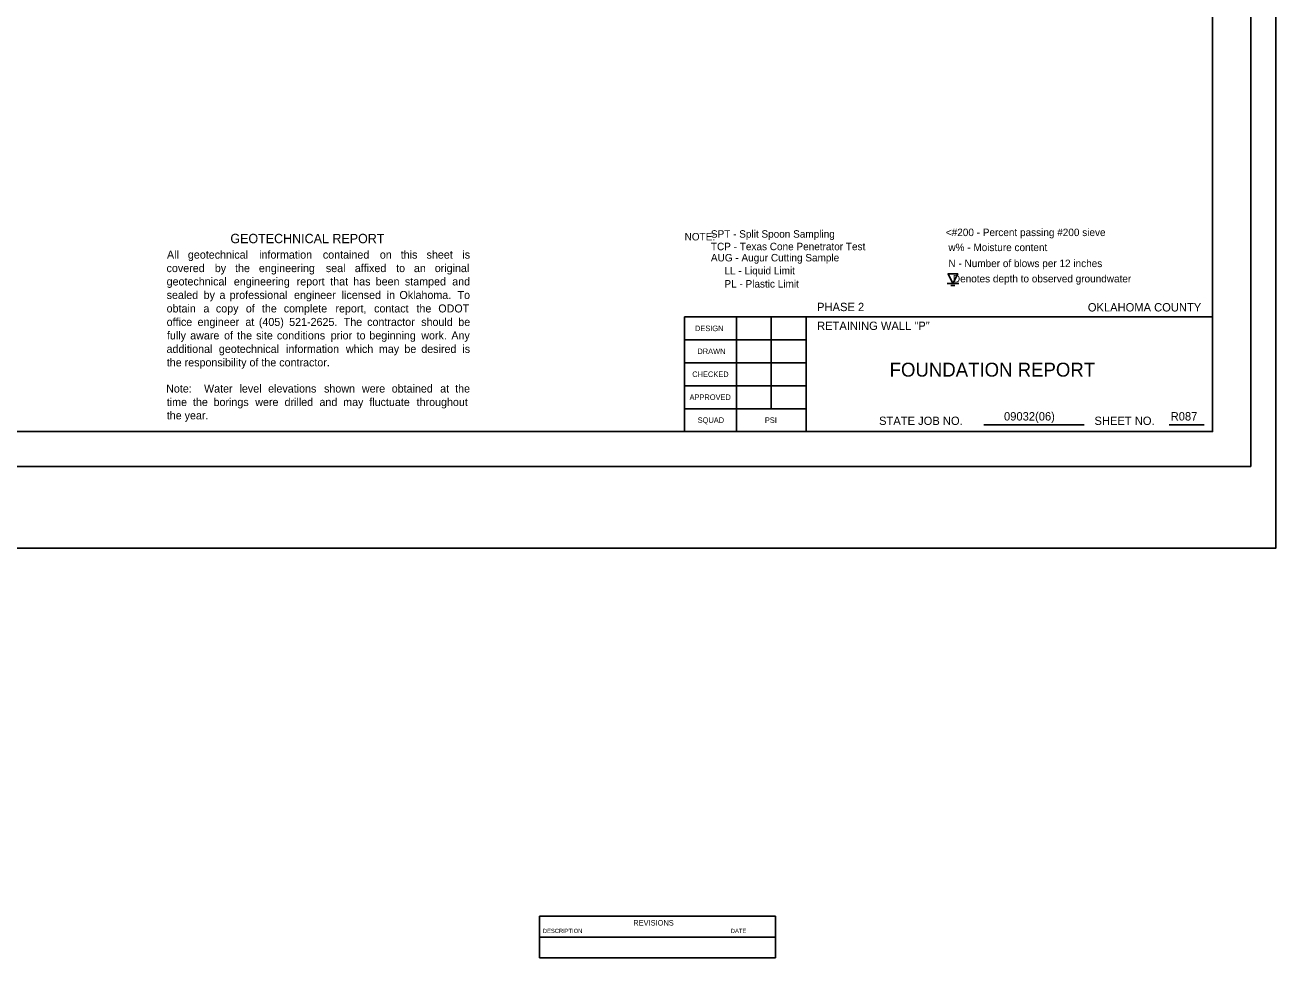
# Model space of a CAD drawing. Extents: x 6.6 to 42.6, y 24.1 to 55.9.
# Drawn here: x 24.62 to 42.62, y 24.08 to 37.49 of the extents above; entities that cross this region are included whole.
import ezdxf

# ---------------------------------------------------------------- set-up
doc = ezdxf.new("R2010")
doc.units = 0
for name, color, linetype in [('4', 7, 'Continuous'), ('REVBLK', 7, 'Continuous'), ('SHT_Plot_Shape_Full', 7, 'Continuous'), ('SHT_Plot_Shape_Half', 7, 'Continuous'), ('SHT_Sheet_Border', 7, 'Continuous'), ('SHT_Standard_Sheet_Lines', 7, 'Continuous'), ('SHT_Standard_Sheet_Txt', 7, 'Continuous'), ('T', 7, 'Continuous'), ('Text', 7, 'Continuous')]:
    doc.layers.add(name, color=color, linetype=linetype)

# ---------------------------------------------------------------- blocks, each defined once
blk = doc.blocks.new('DGRFC_WTLEV1_1')
for points in [[(-0.005, 0), (0.005, 0)], [(0, 0), (0.0042, 0.0083), (-0.0042, 0.0083), (0, 0)], [(-0.0017, -0.0017), (0.0017, -0.0017)]]:
    blk.add_lwpolyline(points)

msp = doc.modelspace()

# ---------------------------------------------------------------- linework, layer by layer
at = {"layer": 'REVBLK'}
for p, q in [((32.025, 24.676), (35.425, 24.676)), ((32.025, 24.676), (32.025, 24.076)), ((35.425, 24.676), (35.425, 24.076)), ((32.025, 24.376), (35.425, 24.376)), ((32.025, 24.076), (35.425, 24.076))]:
    msp.add_line(p, q, dxfattribs=at)
at = {"layer": 'SHT_Plot_Shape_Full'}
msp.add_lwpolyline([(6.624, 53.971), (42.624, 53.971), (42.624, 29.971), (6.624, 29.971)], close=True, dxfattribs=at)
at = {"layer": 'SHT_Plot_Shape_Half'}
msp.add_lwpolyline([(8.262, 53.146), (42.262, 53.146), (42.262, 31.146), (8.262, 31.146)], close=True, dxfattribs=at)
at = {"layer": 'SHT_Sheet_Border'}
for p, q in [((34.112, 31.646), (34.112, 33.296)), ((34.112, 33.296), (41.712, 33.296)), ((35.862, 31.646), (35.862, 33.297))]:
    msp.add_line(p, q, dxfattribs=at)
msp.add_lwpolyline([(10.212, 52.646), (41.712, 52.646), (41.712, 31.646), (10.212, 31.646)], close=True, dxfattribs=at)
at = {"layer": 'SHT_Standard_Sheet_Lines'}
for p, q in [((34.862, 31.646), (34.862, 33.297)), ((35.362, 31.976), (35.362, 33.297)), ((38.422, 31.742), (39.863, 31.742)), ((41.087, 31.742), (41.59, 31.742))]:
    msp.add_line(p, q, dxfattribs=at)
for points in [[(35.862, 32.966), (34.112, 32.966)], [(35.862, 32.636), (34.112, 32.636)], [(35.862, 32.306), (34.112, 32.306)], [(35.862, 31.976), (34.112, 31.976)]]:
    msp.add_lwpolyline(points, dxfattribs=at)

# ---------------------------------------------------------------- block references
at = {"xscale": 16.585714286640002, "yscale": 16.585714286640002}
msp.add_blockref('DGRFC_WTLEV1_1', (37.976, 33.778), dxfattribs=at)

# ---------------------------------------------------------------- texts
at = {"layer": '4'}
msp.add_text('FOUNDATION REPORT', height=0.2, dxfattribs=at).set_placement((37.065, 32.437))
at = {"layer": 'REVBLK'}
for s, height, p in [('DESCRIPTION', 0.06, (32.077, 24.436)), ('REVISIONS', 0.08, (33.376, 24.542)), ('DATE', 0.06, (34.781, 24.436))]:
    msp.add_text(s, height=height, dxfattribs=at).set_placement(p)
at = {"layer": 'SHT_Standard_Sheet_Txt'}
for s, height, p in [('DESIGN', 0.08, (34.264, 33.091)), ('DRAWN', 0.08, (34.299, 32.761)), ('CHECKED', 0.08, (34.225, 32.431)), ('APPROVED', 0.08, (34.186, 32.101)), ('STATE JOB NO.', 0.12, (36.913, 31.742)), ('SHEET NO. ', 0.12, (40.013, 31.742)), ('SQUAD', 0.08, (34.303, 31.771)), ('PSI', 0.08, (35.27, 31.771))]:
    msp.add_text(s, height=height, dxfattribs=at).set_placement(p)
at = {"layer": 'T'}
for s, p in [('PHASE 2', (36.021, 33.379)), ('OKLAHOMA COUNTY', (39.917, 33.374)), ('RETAINING WALL "P" ', (36.021, 33.108)), ('09032(06)', (38.711, 31.806)), ('R087', (41.109, 31.806))]:
    msp.add_text(s, height=0.12, dxfattribs=at).set_placement(p)
at = {"layer": 'Text'}
for s, height, p in [(' <#200 - Percent passing #200 sieve', 0.10752, (37.834, 34.458)), ('GEOTECHNICAL REPORT', 0.1344, (27.579, 34.356)), ('NOTE:', 0.1075, (34.115, 34.396)), ('    SPT - Split Spoon Sampling', 0.10752, (34.334, 34.435)), ('All', 0.1152, (26.667, 34.134)), ('geotechnical', 0.1152, (26.968, 34.134)), ('information', 0.1152, (27.993, 34.134)), ('contained', 0.1152, (28.91, 34.134)), ('on', 0.1152, (29.73, 34.134)), ('this', 0.1152, (30.03, 34.134)), ('sheet', 0.1152, (30.402, 34.134)), ('is ', 0.1152, (30.917, 34.134)), ('    AUG - Augur Cutting Sample', 0.10752, (34.334, 34.094)), ('    TCP - Texas Cone Penetrator Test', 0.10752, (34.334, 34.255)), ('w% - Moisture content', 0.10752, (37.911, 34.242)), ('covered', 0.1152, (26.661, 33.94)), ('by', 0.1152, (27.355, 33.94)), ('the', 0.1152, (27.646, 33.94)), ('engineering', 0.1152, (27.99, 33.94)), ('seal', 0.1152, (28.953, 33.94)), ('affixed', 0.1152, (29.369, 33.94)), ('to', 0.1152, (29.964, 33.94)), ('an', 0.1152, (30.22, 33.94)), ('original ', 0.1152, (30.52, 33.94)), (' LL - Liquid Limit', 0.10752, (34.648, 33.908)), ('N - Number of blows per 12 inches', 0.10752, (37.911, 34.012)), ('geotechnical', 0.1152, (26.662, 33.748)), ('engineering', 0.1152, (27.629, 33.748)), ('report', 0.1152, (28.533, 33.748)), ('that', 0.1152, (29.016, 33.748)), ('has', 0.1152, (29.347, 33.748)), ('been', 0.1152, (29.67, 33.748)), ('stamped', 0.1152, (30.09, 33.748)), ('and ', 0.1152, (30.771, 33.748)), ('    Denotes depth to observed groundwater', 0.10752, (37.816, 33.792)), ('sealed', 0.1152, (26.662, 33.554)), ('by', 0.1152, (27.194, 33.554)), ('professional', 0.1152, (27.569, 33.554)), ('engineer', 0.1152, (28.495, 33.554)), ('licensed', 0.1152, (29.181, 33.554)), ('in', 0.1152, (29.829, 33.554)), ('Oklahoma.', 0.1152, (30.012, 33.554)), ('To ', 0.1152, (30.848, 33.554)), (' PL - Plastic Limit', 0.10752, (34.648, 33.718)), ('obtain', 0.1152, (26.662, 33.36)), ('a', 0.115, (27.422, 33.554)), ('of', 0.1152, (27.802, 33.36)), ('the', 0.1152, (28.033, 33.36)), ('complete', 0.1152, (28.347, 33.36)), ('the', 0.1152, (30.257, 33.36)), ('a', 0.115, (27.191, 33.36)), ('copy', 0.1152, (27.371, 33.36)), ('report,', 0.1152, (29.091, 33.36)), ('contact', 0.1152, (29.647, 33.36)), ('ODOT ', 0.1152, (30.571, 33.36)), ('office', 0.1152, (26.662, 33.166)), ('engineer', 0.1152, (27.107, 33.166)), ('at', 0.1152, (27.795, 33.166)), ('(405)', 0.1152, (27.989, 33.166)), ('521-2625.', 0.1152, (28.425, 33.166)), ('The', 0.1152, (29.21, 33.166)), ('contractor', 0.1152, (29.547, 33.166)), ('should', 0.1152, (30.325, 33.166)), ('be ', 0.1152, (30.859, 33.166)), ('fully', 0.1152, (26.666, 32.972)), ('aware', 0.1152, (27.001, 32.972)), ('of', 0.1152, (27.488, 32.972)), ('the', 0.1152, (27.677, 32.972)), ('site', 0.1152, (27.95, 32.972)), ('conditions', 0.1152, (28.249, 32.972)), ('prior', 0.1152, (29.023, 32.972)), ('to', 0.1152, (29.396, 32.972)), ('beginning', 0.1152, (29.579, 32.972)), ('work.', 0.1152, (30.326, 32.972)), ('Any ', 0.1152, (30.759, 32.972)), ('additional', 0.1152, (26.661, 32.778)), ('geotechnical', 0.1152, (27.414, 32.778)), ('information', 0.1152, (28.381, 32.778)), ('which', 0.1152, (29.241, 32.778)), ('may', 0.1152, (29.716, 32.778)), ('be', 0.1152, (30.083, 32.778)), ('desired', 0.1152, (30.326, 32.778)), ('is ', 0.1152, (30.917, 32.778)), ('the responsibility of the contractor.', 0.1152, (26.664, 32.584)), ('Note:', 0.1152, (26.655, 32.208)), ('Water', 0.1152, (27.2, 32.208)), ('level', 0.1152, (27.711, 32.208)), ('elevations', 0.1152, (28.122, 32.208)), ('shown', 0.1152, (28.927, 32.208)), ('were', 0.1152, (29.472, 32.208)), ('obtained', 0.1152, (29.901, 32.208)), ('at', 0.1152, (30.598, 32.208)), ('the ', 0.1152, (30.813, 32.208)), ('time', 0.1152, (26.664, 32.014)), ('the', 0.1152, (27.041, 32.014)), ('borings', 0.1152, (27.337, 32.014)), ('were', 0.1152, (27.937, 32.014)), ('drilled', 0.1152, (28.359, 32.014)), ('and', 0.1152, (28.861, 32.014)), ('may', 0.1152, (29.202, 32.014)), ('fluctuate', 0.1152, (29.578, 32.014)), ('throughout ', 0.1152, (30.259, 32.014)), ('the year.', 0.1152, (26.664, 31.822))]:
    msp.add_text(s, height=height, dxfattribs=at).set_placement(p)

doc.saveas('drawing.dxf')
